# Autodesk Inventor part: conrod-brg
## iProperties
Created: 2002-08
Part Number: conrod-brg
Document SubType Name: Modeling
Designer: t_munrn
Density: 1 g/cm^3
Control State: 0
Master: False
Checked Out: False
Shininess: 64.0
Length Units: 11269
Angle Units: 11279
Time Units: 11290
Mass Units: 11283
Length Display Precision: 3
Angle Display Precision: 2
Density: 0.0
Volumn: 0.0
Area: 0.0
PropertySet Name: Model Information
Author: t_munrn
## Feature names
1. Extrusion1
2. Chamfer1
3. Extrusion2
